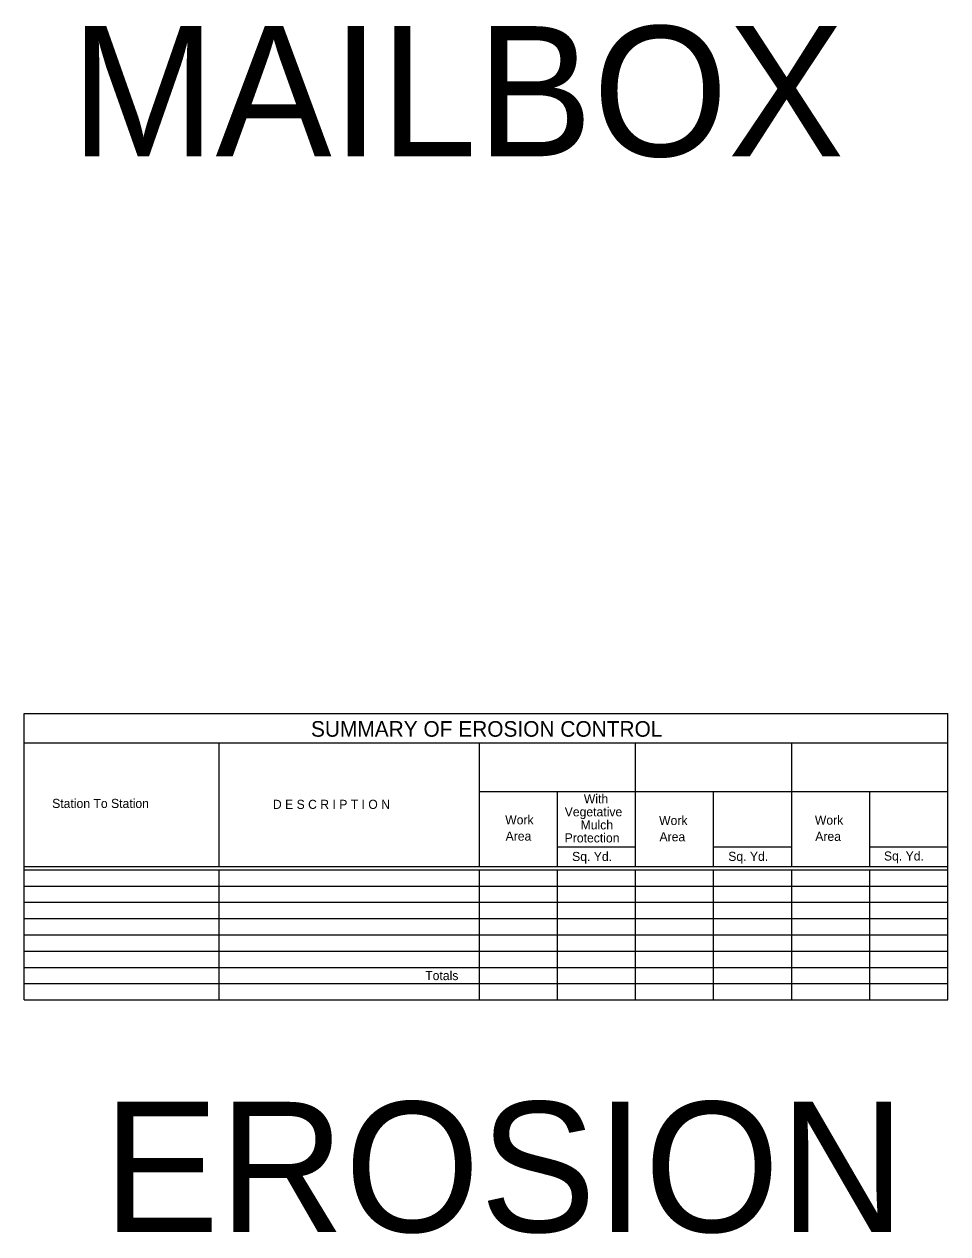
# Model space of a CAD drawing. Extents: x 1790274 to 1791453, y 1790011 to 1790884.
# Drawn here: x 1791303.5 to 1791445.5, y 1790480 to 1790665.8 of the extents above; entities that cross this region are included whole.
import ezdxf

# ---------------------------------------------------------------- set-up
doc = ezdxf.new("R2010")
doc.units = 0
doc.layers.add('Level 1', color=7, linetype='Continuous')
doc.layers.add('Level 2', color=7, linetype='Continuous')

msp = doc.modelspace()

# ---------------------------------------------------------------- linework, layer by layer
at = {"layer": 'Level 1'}
for p, q in [((1791303.51, 1790515.92), (1791303.51, 1790559.92)), ((1791303.51, 1790559.92), (1791445.51, 1790559.92)), ((1791445.51, 1790515.92), (1791445.51, 1790559.92)), ((1791303.51, 1790555.42), (1791445.51, 1790555.42)), ((1791333.51, 1790536.42), (1791333.51, 1790555.42)), ((1791373.51, 1790536.42), (1791373.51, 1790555.42)), ((1791397.51, 1790536.42), (1791397.51, 1790555.42)), ((1791421.51, 1790536.42), (1791421.51, 1790555.42)), ((1791373.51, 1790547.92), (1791445.51, 1790547.92)), ((1791385.51, 1790536.42), (1791385.51, 1790547.92)), ((1791409.51, 1790536.42), (1791409.51, 1790547.92)), ((1791433.51, 1790536.42), (1791433.51, 1790547.92)), ((1791385.51, 1790539.42), (1791397.51, 1790539.42)), ((1791409.51, 1790539.42), (1791421.51, 1790539.42)), ((1791433.51, 1790539.42), (1791445.51, 1790539.42)), ((1791303.51, 1790536.42), (1791445.51, 1790536.42)), ((1791303.51, 1790535.92), (1791445.51, 1790535.92)), ((1791333.51, 1790515.92), (1791333.51, 1790535.92)), ((1791373.51, 1790515.92), (1791373.51, 1790535.92)), ((1791385.51, 1790515.92), (1791385.51, 1790535.92)), ((1791397.51, 1790515.92), (1791397.51, 1790535.92)), ((1791409.51, 1790515.92), (1791409.51, 1790535.92)), ((1791421.51, 1790515.92), (1791421.51, 1790535.92)), ((1791433.51, 1790515.92), (1791433.51, 1790535.92)), ((1791303.51, 1790533.42), (1791445.51, 1790533.42)), ((1791303.51, 1790530.92), (1791445.51, 1790530.92)), ((1791303.51, 1790528.42), (1791445.51, 1790528.42)), ((1791303.51, 1790525.92), (1791445.51, 1790525.92)), ((1791303.51, 1790523.42), (1791445.51, 1790523.42)), ((1791303.51, 1790520.92), (1791445.51, 1790520.92)), ((1791303.51, 1790518.42), (1791445.51, 1790518.42)), ((1791303.51, 1790515.92), (1791445.51, 1790515.92))]:
    msp.add_line(p, q, dxfattribs=at)

# ---------------------------------------------------------------- texts
at = {"layer": 'Level 2'}
for s, height, p in [('MAILBOX', 20, (1791310.66, 1790645.55)), ('SUMMARY OF EROSION CONTROL', 2.4, (1791347.6, 1790556.36)), ('Station To Station', 1.4, (1791307.81, 1790545.41)), ('D E S C R I P T I O N', 1.4, (1791341.75, 1790545.27)), ('With', 1.4, (1791389.55, 1790546.12)), ('Work', 1.4, (1791377.46, 1790542.89)), ('Vegetative', 1.4, (1791386.61, 1790544.12)), ('Work', 1.4, (1791401.12, 1790542.79)), ('Work', 1.4, (1791425.07, 1790542.85)), ('Mulch', 1.4, (1791389.05, 1790542.12)), ('Area', 1.4, (1791377.52, 1790540.39)), ('Protection', 1.4, (1791386.6, 1790540.12)), ('Area', 1.4, (1791401.18, 1790540.29)), ('Area', 1.4, (1791425.13, 1790540.35)), ('Sq. Yd.', 1.4, (1791387.75, 1790537.26)), ('Sq. Yd.', 1.4, (1791411.75, 1790537.28)), ('Sq. Yd.', 1.4, (1791435.69, 1790537.34)), ('Totals', 1.4, (1791365.17, 1790518.96)), ('EROSION', 20, (1791315.62, 1790480.26))]:
    msp.add_text(s, height=height, dxfattribs=at).set_placement(p)

doc.saveas('drawing.dxf')
